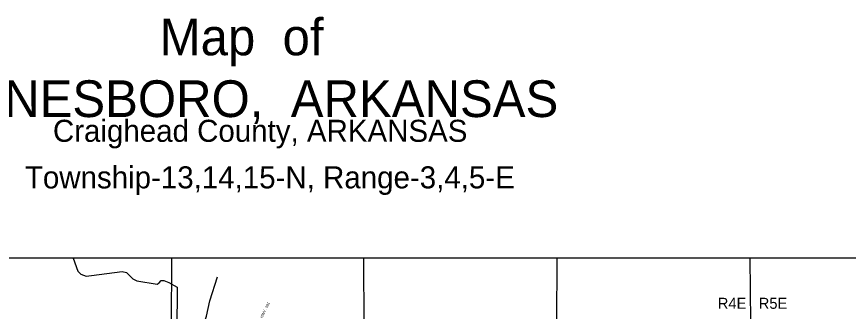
# Model space of a CAD drawing. Extents: x 1670563 to 1761545, y 515755 to 578944.
# Drawn here: x 1705739 to 1728380, y 570923 to 578944 of the extents above; entities that cross this region are included whole.
import ezdxf

# ---------------------------------------------------------------- set-up
doc = ezdxf.new("R2010")
doc.units = 0
for name, color, linetype in [('4_text', 7, 'Continuous'), ('4_TwnRge', 7, 'Continuous'), ('5_sectionlines', 7, 'Continuous'), ('SHP_LINE', 7, 'Continuous'), ('STREETCL', 7, 'Continuous'), ('STRNAMES', 7, 'Continuous')]:
    doc.layers.add(name, color=color, linetype=linetype)

# ---------------------------------------------------------------- blocks, each defined once
blk = doc.blocks.new('BORDER02')
blk.add_lwpolyline([(1670684, 515755), (1761545, 515755), (1761545, 572369), (1670684, 572369)], close=True)
blk = doc.blocks.new('A$C7196343B')
at = {"layer": '4_text'}
blk.add_text('R4E   R5E', height=300, dxfattribs=at).set_placement((53777, 54746))

msp = doc.modelspace()

# ---------------------------------------------------------------- linework, layer by layer
at = {"layer": '4_TwnRge'}
msp.add_lwpolyline([(1725700, 572370), (1725715, 570631), (1725733, 565333)], dxfattribs=at)
at = {"layer": '5_sectionlines'}
for points in [[(1709953, 572370), (1709950, 570539), (1710002, 565251)], [(1715208, 565228), (1715197, 570541), (1715193, 572370)], [(1720445, 572370), (1720439, 570592), (1720455, 565306)]]:
    msp.add_lwpolyline(points, dxfattribs=at)
at = {"layer": 'SHP_LINE'}
for p, q in [((1707278, 572371), (1707409, 572017)), ((1707409, 572017), (1707483, 571936)), ((1707483, 571936), (1707632, 571882)), ((1707632, 571882), (1707780, 571902)), ((1707780, 571902), (1708611, 572004)), ((1708611, 572004), (1708733, 571977)), ((1708733, 571977), (1708841, 571875)), ((1708841, 571875), (1708902, 571808)), ((1708902, 571808), (1709010, 571754)), ((1709010, 571754), (1709564, 571659)), ((1709564, 571659), (1709618, 571700)), ((1709618, 571700), (1709672, 571767)), ((1709672, 571767), (1709747, 571767)), ((1709747, 571767), (1709882, 571713)), ((1709882, 571713), (1710105, 571578)), ((1710105, 571578), (1710098, 569742))]:
    msp.add_line(p, q, dxfattribs=at)
msp.add_lwpolyline([(1709570, 568128), (1709720, 568471), (1710362, 569655), (1710830, 570551), (1710904, 570794), (1710999, 571213), (1711208, 571861)], dxfattribs=at)

# ---------------------------------------------------------------- block references
msp.add_blockref('A$C7196343B', (1671047, 516246))
at = {"layer": 'STREETCL'}
msp.add_blockref('BORDER02', (0, 0), dxfattribs=at)

# ---------------------------------------------------------------- texts
for s, height, p in [('                 Map  of', 1000, (1703318, 577892)), (' JONESBORO,  ARKANSAS', 1000, (1703318, 576211)), ('Craighead County, ARKANSAS', 600, (1706727, 575537)), ('Township-13,14,15-N, Range-3,4,5-E', 600, (1705964, 574270))]:
    msp.add_text(s, height=height).set_placement(p)
at = {"layer": 'STRNAMES'}
msp.add_text('HWY. 351', height=75, rotation=64.6333, dxfattribs=at).set_placement((1712434, 570729))

doc.saveas('drawing.dxf')
